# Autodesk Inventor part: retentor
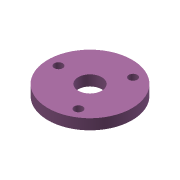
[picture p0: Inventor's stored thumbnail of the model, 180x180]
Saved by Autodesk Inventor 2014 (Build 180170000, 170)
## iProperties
Created: 2012-09
Part Number: retentor
Material: Generic
Document SubType Name: Modeling
Designer: TR-06
Density: 1 g/cm^3
Appearance: Default
Author: TR-06
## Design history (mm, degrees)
sketch "Sketch1"
  geometry: C1 r 100 at (0, 0); C2 r 28 at (0, 0); 1 further point
  constraints: 2 centre point, 2 coincident
  dimensions: "d0" = 200 diameter of C1; "d1" = 56 diameter of C2
extrude "Extrusion1" new body sketch "Sketch1" stored distance "d2" = 25; taper "d3" = 0 deg
sketch "Sketch2" dims "d4" = 150
  geometry: C1 r 100 at (0, 0) reference; C2 r 10.15 at (-75, 0); C3 r 10.15 at (37.5, 64.952); C4 r 10.15 at (37.5, -64.952); 6 further points
  constraints: 6 coincident, 3 centre point, 1 horizontal alignment, 7 other
  dimensions: "d7" = 360 deg dimension on point (0, 0) point (-75, 0) (derived); "d9" = 20.3 diameter of C2; "d10" = 20.3 diameter of C3; "d11" = 20.3 diameter of C4
extrude "Extrusion2" cut sketch "Sketch2" stored distance "d12" = 25; taper "d13" = 0 deg
body "Solid1"
